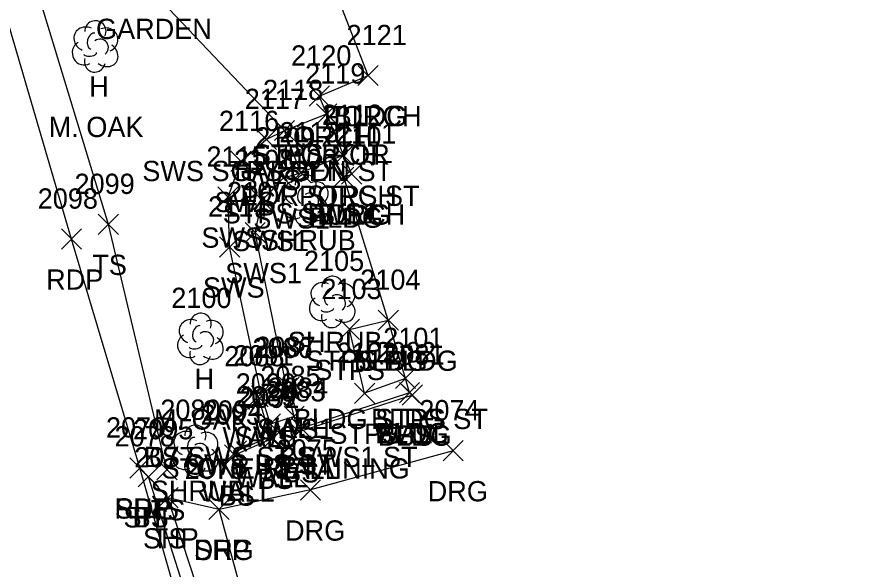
# Model space of a CAD drawing. Extents: x 1620157 to 1620595, y 115111 to 117885.
# Drawn here: x 1620251.8 to 1620336.2, y 115691.4 to 115746 of the extents above; entities that cross this region are included whole.
import ezdxf

# ---------------------------------------------------------------- set-up
doc = ezdxf.new("R2010")
doc.units = 0
for name, color, linetype in [('L_A', 7, 'Continuous'), ('L_C', 7, 'Continuous'), ('L_I', 7, 'Continuous'), ('L_TIC', 7, 'Continuous'), ('LAPB', 7, 'Continuous'), ('LBC', 7, 'Continuous'), ('LBF', 7, 'Continuous'), ('LELB', 7, 'Continuous'), ('LSH', 7, 'Continuous'), ('LTD', 7, 'Continuous'), ('LW', 7, 'Continuous'), ('P_A', 7, 'Continuous'), ('P_I', 7, 'Continuous'), ('P_TIC', 7, 'Continuous'), ('PET', 7, 'Continuous'), ('PSP', 7, 'Continuous'), ('R_A', 7, 'Continuous'), ('R_I', 7, 'Continuous'), ('R_TIC', 7, 'Continuous'), ('RDG', 7, 'Continuous'), ('RSW', 7, 'Continuous')]:
    doc.layers.add(name, color=color, linetype=linetype)

msp = doc.modelspace()

# ---------------------------------------------------------------- linework, layer by layer
at = {"layer": 'L_TIC'}
for points in [[(1620285.479, 115739.19), (1620287.479, 115741.19)], [(1620287.479, 115739.19), (1620285.479, 115741.19)], [(1620285.479, 115739.19), (1620287.479, 115741.19)], [(1620287.479, 115739.19), (1620285.479, 115741.19)], [(1620280.656, 115737.169), (1620282.656, 115739.169)], [(1620282.656, 115737.169), (1620280.656, 115739.169)], [(1620281.394, 115735.396), (1620283.394, 115737.396)], [(1620283.394, 115735.396), (1620281.394, 115737.396)], [(1620281.394, 115735.396), (1620283.394, 115737.396)], [(1620283.394, 115735.396), (1620281.394, 115737.396)], [(1620277.224, 115733.768), (1620279.224, 115735.768)], [(1620279.224, 115733.768), (1620277.224, 115735.768)], [(1620277.224, 115733.768), (1620279.224, 115735.768)], [(1620279.224, 115733.768), (1620277.224, 115735.768)], [(1620283.041, 115731.322), (1620285.041, 115733.322)], [(1620285.041, 115731.322), (1620283.041, 115733.322)], [(1620283.041, 115731.322), (1620285.041, 115733.322)], [(1620285.041, 115731.322), (1620283.041, 115733.322)], [(1620278.843, 115729.594), (1620280.843, 115731.594)], [(1620280.843, 115729.594), (1620278.843, 115731.594)], [(1620283.066, 115729.16), (1620285.066, 115731.16)], [(1620285.066, 115729.16), (1620283.066, 115731.16)], [(1620283.863, 115729.466), (1620285.863, 115731.466)], [(1620285.863, 115729.466), (1620283.863, 115731.466)], [(1620283.863, 115729.466), (1620285.863, 115731.466)], [(1620285.863, 115729.466), (1620283.863, 115731.466)], [(1620259.835, 115724.502), (1620261.835, 115726.502)], [(1620261.835, 115724.502), (1620259.835, 115726.502)], [(1620287.473, 115715.044), (1620289.473, 115717.044)], [(1620289.473, 115715.044), (1620287.473, 115717.044)], [(1620287.473, 115715.044), (1620289.473, 115717.044)], [(1620289.473, 115715.044), (1620287.473, 115717.044)], [(1620283.642, 115714.129), (1620285.642, 115716.129)], [(1620285.642, 115714.129), (1620283.642, 115716.129)], [(1620289.174, 115709.294), (1620291.174, 115711.294)], [(1620291.174, 115709.294), (1620289.174, 115711.294)], [(1620289.174, 115709.294), (1620291.174, 115711.294)], [(1620291.174, 115709.294), (1620289.174, 115711.294)], [(1620277.686, 115708.413), (1620279.686, 115710.413)], [(1620279.686, 115708.413), (1620277.686, 115710.413)], [(1620285.139, 115707.835), (1620287.139, 115709.835)], [(1620287.139, 115707.835), (1620285.139, 115709.835)], [(1620289.565, 115707.888), (1620291.565, 115709.888)], [(1620291.565, 115707.888), (1620289.565, 115709.888)], [(1620289.565, 115707.888), (1620291.565, 115709.888)], [(1620291.565, 115707.888), (1620289.565, 115709.888)], [(1620274.614, 115707.49), (1620276.614, 115709.49)], [(1620276.614, 115707.49), (1620274.614, 115709.49)], [(1620289.85, 115707.651), (1620291.85, 115709.651)], [(1620291.85, 115707.651), (1620289.85, 115709.651)], [(1620289.85, 115707.651), (1620291.85, 115709.651)], [(1620291.85, 115707.651), (1620289.85, 115709.651)], [(1620278.18, 115705.543), (1620280.18, 115707.543)], [(1620280.18, 115705.543), (1620278.18, 115707.543)], [(1620275.83, 115704.795), (1620277.83, 115706.795)], [(1620277.83, 115704.795), (1620275.83, 115706.795)], [(1620278.906, 115704.377), (1620280.906, 115706.377)], [(1620280.906, 115704.377), (1620278.906, 115706.377)], [(1620275.799, 115703.54), (1620277.799, 115705.54)], [(1620277.799, 115703.54), (1620275.799, 115705.54)], [(1620278.653, 115704.023), (1620280.653, 115706.023)], [(1620280.653, 115704.023), (1620278.653, 115706.023)], [(1620276.094, 115703.385), (1620278.094, 115705.385)], [(1620278.094, 115703.385), (1620276.094, 115705.385)], [(1620272.482, 115702.127), (1620274.482, 115704.127)], [(1620274.482, 115702.127), (1620272.482, 115704.127)], [(1620272.286, 115701.732), (1620274.286, 115703.732)], [(1620274.286, 115701.732), (1620272.286, 115703.732)], [(1620265.612, 115700.283), (1620267.612, 115702.283)], [(1620267.612, 115700.283), (1620265.612, 115702.283)], [(1620263.785, 115699.582), (1620265.785, 115701.582)], [(1620265.785, 115699.582), (1620263.785, 115701.582)], [(1620265.718, 115697.512), (1620267.718, 115699.512)], [(1620267.718, 115697.512), (1620265.718, 115699.512)]]:
    msp.add_lwpolyline(points, dxfattribs=at)
at = {"layer": 'LAPB'}
msp.add_lwpolyline([(1620278.224, 115734.768), (1620264.941, 115748.796), (1620257.681, 115770.754)], dxfattribs=at)
at = {"layer": 'LBC'}
for points in [[(1620286.479, 115740.19), (1620278.676, 115760.26), (1620273.221, 115758.055), (1620271.644, 115761.629), (1620268.392, 115762.369), (1620266.542, 115766.833), (1620268.468, 115769.831), (1620266.748, 115774.206), (1620264.771, 115779.101), (1620264.248, 115780.999)], [(1620290.85, 115708.651), (1620290.565, 115708.888), (1620290.174, 115710.294), (1620288.473, 115716.044), (1620284.066, 115730.16), (1620284.863, 115730.466)]]:
    msp.add_lwpolyline(points, dxfattribs=at)
at = {"layer": 'LBF'}
for points in [[(1620284.863, 115730.466), (1620284.041, 115732.322), (1620282.394, 115736.396), (1620281.656, 115738.169), (1620286.479, 115740.19)], [(1620284.041, 115732.322), (1620279.843, 115730.594), (1620278.224, 115734.768), (1620282.394, 115736.396)], [(1620290.174, 115710.294), (1620286.139, 115708.835), (1620284.642, 115715.129), (1620288.473, 115716.044)]]:
    msp.add_lwpolyline(points, dxfattribs=at)
at = {"layer": 'LELB'}
for points in [[(1620266.612, 115701.283), (1620260.835, 115725.502), (1620244.29, 115779.748)], [(1620290.85, 115708.651), (1620279.653, 115705.023), (1620279.18, 115706.543)], [(1620276.83, 115705.795), (1620277.094, 115704.385), (1620273.286, 115702.732)], [(1620284.85, 115634.911), (1620272.284, 115677.072), (1620264.785, 115700.582)], [(1620274.466, 115674.837), (1620266.718, 115698.512)]]:
    msp.add_lwpolyline(points, dxfattribs=at)
at = {"layer": 'LSH'}
for p, q in [((1620280.261, 115727.94), (1620280.261, 115727.94)), ((1620280.261, 115727.94), (1620280.261, 115727.94)), ((1620282.915, 115717.895), (1620282.915, 115717.895)), ((1620282.915, 115717.895), (1620282.915, 115717.895)), ((1620269.385, 115703.207), (1620269.385, 115703.207)), ((1620269.385, 115703.207), (1620269.385, 115703.207))]:
    msp.add_line(p, q, dxfattribs=at)
for centre in [(1620280.308, 115729.374), (1620282.961, 115719.329), (1620269.432, 115704.641)]:
    msp.add_arc(centre, 1.047, 335.52715, 180.95627, dxfattribs=at)
for centre, major_axis, ratio, start_param, end_param in [((1620279.47, 115728.606), (1.21, -0.512), 0.895232, 1.570796, 4.712389), ((1620280.053, 115728.398), (-0.208, -0.792), 0.645439, 3.141593, 6.283185), ((1620281.303, 115728.523), (-1.141, -0.483), 0.949671, 1.570796, 4.712389), ((1620280.762, 115727.773), (-0.5, 0.667), 0.989748, 3.141593, 6.283185), ((1620279.178, 115727.231), (0.584, -1.042), 0.959034, 3.141593, 6.283185), ((1620281.262, 115727.106), (-1.09, 0.792), 0.841452, 1.570796, 4.712389), ((1620280.262, 115726.44), (0.265, 1.061), 0.942809, 1.570796, 4.712389), ((1620279.803, 115727.19), (-0.625, -0.083), 0.423636, 0, 3.141593), ((1620282.123, 115718.561), (1.21, -0.512), 0.895232, 1.570796, 4.712389), ((1620282.706, 115718.353), (-0.208, -0.792), 0.645439, 3.141593, 6.283185), ((1620283.956, 115718.478), (-1.141, -0.483), 0.949671, 1.570796, 4.712389), ((1620281.832, 115717.186), (0.584, -1.042), 0.959034, 3.141593, 6.283185), ((1620283.415, 115717.728), (-0.5, 0.667), 0.989748, 3.141593, 6.283185), ((1620283.915, 115717.062), (-1.09, 0.792), 0.841452, 1.570796, 4.712389), ((1620282.915, 115716.395), (0.265, 1.061), 0.942809, 1.570796, 4.712389), ((1620282.457, 115717.145), (-0.625, -0.083), 0.423636, 0, 3.141593), ((1620268.593, 115703.873), (1.21, -0.512), 0.895232, 1.570796, 4.712389), ((1620270.427, 115703.79), (-1.141, -0.483), 0.949671, 1.570796, 4.712389), ((1620269.177, 115703.665), (-0.208, -0.792), 0.645439, 3.141593, 6.283185), ((1620269.885, 115703.04), (-0.5, 0.667), 0.989748, 3.141593, 6.283185), ((1620268.302, 115702.498), (0.584, -1.042), 0.959034, 3.141593, 6.283185), ((1620270.385, 115702.373), (-1.09, 0.792), 0.841452, 1.570796, 4.712389), ((1620268.927, 115702.457), (-0.625, -0.083), 0.423636, 0, 3.141593), ((1620269.385, 115701.707), (0.265, 1.061), 0.942809, 1.570796, 4.712389)]:
    msp.add_ellipse(centre, major_axis=major_axis, ratio=ratio, start_param=start_param, end_param=end_param, dxfattribs=at)
at = {"layer": 'LTD'}
for p, q in [((1620259.508, 115743.117), (1620259.508, 115743.117)), ((1620259.508, 115743.117), (1620259.508, 115743.117)), ((1620269.905, 115714.244), (1620269.905, 115714.244)), ((1620269.905, 115714.244), (1620269.905, 115714.244))]:
    msp.add_line(p, q, dxfattribs=at)
for centre in [(1620259.555, 115744.551), (1620269.952, 115715.678)]:
    msp.add_arc(centre, 1.047, 335.52715, 180.95627, dxfattribs=at)
for centre, major_axis, ratio, start_param, end_param in [((1620258.717, 115743.783), (1.21, -0.512), 0.895232, 1.570796, 4.712389), ((1620259.3, 115743.575), (-0.208, -0.792), 0.645439, 3.141593, 6.283185), ((1620260.55, 115743.7), (-1.141, -0.483), 0.949671, 1.570796, 4.712389), ((1620260.008, 115742.95), (-0.5, 0.667), 0.989748, 3.141593, 6.283185), ((1620258.425, 115742.408), (0.584, -1.042), 0.959034, 3.141593, 6.283185), ((1620260.508, 115742.284), (-1.09, 0.792), 0.841452, 1.570796, 4.712389), ((1620259.509, 115741.617), (0.265, 1.061), 0.942809, 1.570796, 4.712389), ((1620259.05, 115742.367), (-0.625, -0.083), 0.423636, 0, 3.141593), ((1620269.114, 115714.91), (1.21, -0.512), 0.895232, 1.570796, 4.712389), ((1620270.947, 115714.827), (-1.141, -0.483), 0.949671, 1.570796, 4.712389), ((1620269.697, 115714.702), (-0.208, -0.792), 0.645439, 3.141593, 6.283185), ((1620270.405, 115714.077), (-0.5, 0.667), 0.989748, 3.141593, 6.283185), ((1620268.822, 115713.535), (0.584, -1.042), 0.959034, 3.141593, 6.283185), ((1620270.905, 115713.411), (-1.09, 0.792), 0.841452, 1.570796, 4.712389), ((1620269.447, 115713.494), (-0.625, -0.083), 0.423636, 0, 3.141593), ((1620269.906, 115712.744), (0.265, 1.061), 0.942809, 1.570796, 4.712389)]:
    msp.add_ellipse(centre, major_axis=major_axis, ratio=ratio, start_param=start_param, end_param=end_param, dxfattribs=at)
at = {"layer": 'LW'}
for points in [[(1620290.565, 115708.888), (1620279.906, 115705.377), (1620278.686, 115709.413)], [(1620275.614, 115708.49), (1620276.799, 115704.54), (1620273.482, 115703.127)]]:
    msp.add_lwpolyline(points, dxfattribs=at)
at = {"layer": 'P_TIC'}
for points in [[(1620256.196, 115723.05), (1620258.196, 115725.05)], [(1620258.196, 115723.05), (1620256.196, 115725.05)], [(1620262.941, 115700.458), (1620264.941, 115702.458)], [(1620264.941, 115700.458), (1620262.941, 115702.458)], [(1620262.941, 115700.458), (1620264.941, 115702.458)], [(1620264.941, 115700.458), (1620262.941, 115702.458)], [(1620263.785, 115699.582), (1620265.785, 115701.582)], [(1620265.785, 115699.582), (1620263.785, 115701.582)], [(1620265.718, 115697.512), (1620267.718, 115699.512)], [(1620267.718, 115697.512), (1620265.718, 115699.512)], [(1620270.765, 115696.364), (1620272.765, 115698.364)], [(1620272.765, 115696.364), (1620270.765, 115698.364)]]:
    msp.add_lwpolyline(points, dxfattribs=at)
at = {"layer": 'PET'}
msp.add_lwpolyline([(1620336.223, 115456.795), (1620332.523, 115469.32), (1620324.589, 115500.95), (1620318.089, 115527.231), (1620313.062, 115541.759), (1620309.737, 115554.427), (1620302.898, 115574.327), (1620297.627, 115590.435), (1620296.31, 115595.422), (1620295.446, 115598.549), (1620285.025, 115631.411), (1620284.003, 115634.579), (1620271.049, 115676.547), (1620263.941, 115701.458), (1620257.196, 115724.05), (1620247.856, 115755.871), (1620237.557, 115791.502), (1620229.867, 115820.365), (1620222.522, 115845.456)], dxfattribs=at)
at = {"layer": 'PSP'}
msp.add_lwpolyline([(1620284.003, 115634.579), (1620284.85, 115634.911), (1620285.305, 115636.206), (1620274.466, 115674.837), (1620275.53, 115678.066), (1620276.548, 115679.801), (1620271.765, 115697.364), (1620266.718, 115698.512), (1620264.785, 115700.582), (1620263.941, 115701.458)], dxfattribs=at)
at = {"layer": 'R_TIC'}
for points in [[(1620277.224, 115733.768), (1620279.224, 115735.768)], [(1620279.224, 115733.768), (1620277.224, 115735.768)], [(1620275.422, 115732.886), (1620277.422, 115734.886)], [(1620277.422, 115732.886), (1620275.422, 115734.886)], [(1620272.928, 115730.714), (1620274.928, 115732.714)], [(1620274.928, 115730.714), (1620272.928, 115732.714)], [(1620277.109, 115729.087), (1620279.109, 115731.087)], [(1620279.109, 115729.087), (1620277.109, 115731.087)], [(1620278.843, 115729.594), (1620280.843, 115731.594)], [(1620280.843, 115729.594), (1620278.843, 115731.594)], [(1620271.646, 115727.194), (1620273.646, 115729.194)], [(1620273.646, 115727.194), (1620271.646, 115729.194)], [(1620275.018, 115726.863), (1620277.018, 115728.863)], [(1620277.018, 115726.863), (1620275.018, 115728.863)], [(1620274.331, 115723.694), (1620276.331, 115725.694)], [(1620276.331, 115723.694), (1620274.331, 115725.694)], [(1620271.799, 115722.267), (1620273.799, 115724.267)], [(1620273.799, 115722.267), (1620271.799, 115724.267)], [(1620277.457, 115708.306), (1620279.457, 115710.306)], [(1620279.457, 115708.306), (1620277.457, 115710.306)], [(1620274.953, 115707.566), (1620276.953, 115709.566)], [(1620276.953, 115707.566), (1620274.953, 115709.566)], [(1620278.18, 115705.543), (1620280.18, 115707.543)], [(1620280.18, 115705.543), (1620278.18, 115707.543)], [(1620278.18, 115705.543), (1620280.18, 115707.543)], [(1620280.18, 115705.543), (1620278.18, 115707.543)], [(1620275.83, 115704.795), (1620277.83, 115706.795)], [(1620277.83, 115704.795), (1620275.83, 115706.795)], [(1620293.874, 115702.163), (1620295.874, 115704.163)], [(1620295.874, 115702.163), (1620293.874, 115704.163)], [(1620279.788, 115698.282), (1620281.788, 115700.282)], [(1620281.788, 115698.282), (1620279.788, 115700.282)], [(1620270.765, 115696.364), (1620272.765, 115698.364)], [(1620272.765, 115696.364), (1620270.765, 115698.364)]]:
    msp.add_lwpolyline(points, dxfattribs=at)
at = {"layer": 'RDG'}
msp.add_lwpolyline([(1620294.874, 115703.163), (1620280.788, 115699.282), (1620271.765, 115697.364)], dxfattribs=at)
at = {"layer": 'RSW'}
for points in [[(1620279.18, 115706.543), (1620276.83, 115705.795), (1620275.953, 115708.566), (1620272.799, 115723.267), (1620272.646, 115728.194), (1620273.928, 115731.714), (1620276.422, 115733.886), (1620278.224, 115734.768)], [(1620279.18, 115706.543), (1620278.457, 115709.306), (1620275.331, 115724.694), (1620276.018, 115727.863), (1620278.109, 115730.087), (1620279.843, 115730.594)]]:
    msp.add_lwpolyline(points, dxfattribs=at)

# ---------------------------------------------------------------- texts
at = {"layer": 'L_A'}
for s, p in [('GARDEN', (1620259.611, 115743.796)), ('H', (1620258.941, 115738.117)), ('PORCH', (1620282.101, 115735.19)), ('BLDG', (1620283.069, 115735.19)), ('PORCH', (1620277.278, 115733.169)), ('STPS POR', (1620275.094, 115731.396)), ('PORCH', (1620278.016, 115731.396)), ('SWS STPS GDN ST', (1620264.185, 115729.768)), ('GARDEN', (1620272.893, 115729.768)), ('POR STPS ST', (1620273.876, 115727.322)), ('PORCH', (1620279.663, 115727.322)), ('STPS SWS1', (1620272.127, 115725.594)), ('PORCH', (1620280.485, 115725.466)), ('BLDG', (1620281.454, 115725.466)), ('BLDG', (1620280.656, 115725.16)), ('SHRUB', (1620275.891, 115722.94)), ('TS', (1620259.244, 115720.502)), ('SHRUB', (1620278.545, 115712.895)), ('STPS BLDG', (1620280.308, 115711.044)), ('BLDG', (1620285.064, 115711.044)), ('STPS', (1620281.161, 115710.129)), ('H', (1620269.338, 115709.244)), ('BLDG STPS ST', (1620279.142, 115705.294)), ('BLDG', (1620286.764, 115705.294)), ('WALL', (1620275.174, 115704.413)), ('STPS', (1620282.659, 115703.835)), ('WALL', (1620287.053, 115703.888)), ('BLDG', (1620287.155, 115703.888)), ('BLDG', (1620287.441, 115703.651)), ('BS', (1620289.291, 115703.651)), ('WALL', (1620272.102, 115703.49)), ('BS', (1620277.621, 115701.543)), ('BS', (1620275.271, 115700.795)), ('WALL', (1620276.394, 115700.377)), ('WALL', (1620273.287, 115699.54)), ('BS', (1620275.535, 115699.385)), ('BS', (1620278.094, 115700.023)), ('SHRUB', (1620265.015, 115698.207)), ('WALL', (1620269.971, 115698.127)), ('BS', (1620271.727, 115697.732)), ('TS', (1620265.021, 115696.283)), ('BS', (1620263.226, 115695.582)), ('TS', (1620265.128, 115693.512))]:
    msp.add_text(s, height=2, dxfattribs=at).set_placement(p)
at = {"layer": 'L_C'}
for s, p in [('M. OAK', (1620254.942, 115734.117)), ('M. OAK', (1620265.338, 115705.244)), ('STONE RETAINING', (1620266.08, 115700.413))]:
    msp.add_text(s, height=2, dxfattribs=at).set_placement(p)
at = {"layer": 'L_I'}
for s, p in [('2121', (1620284.353, 115743.19)), ('2121', (1620284.353, 115743.19)), ('2120', (1620278.877, 115741.169)), ('2119', (1620280.26, 115739.396)), ('2119', (1620280.26, 115739.396)), ('2118', (1620276.098, 115737.768)), ('2118', (1620276.098, 115737.768)), ('2112', (1620281.915, 115735.322)), ('2112', (1620281.915, 115735.322)), ('2113', (1620277.717, 115733.594)), ('2110', (1620281.853, 115733.16)), ('2111', (1620283.305, 115733.466)), ('2111', (1620283.305, 115733.466)), ('2106', (1620277.435, 115730.94)), ('2099', (1620257.488, 115728.502)), ('2105', (1620280.143, 115720.895)), ('2104', (1620285.702, 115719.044)), ('2104', (1620285.702, 115719.044)), ('2103', (1620281.87, 115718.129)), ('2100', (1620267.047, 115717.244)), ('2101', (1620287.969, 115713.294)), ('2101', (1620287.969, 115713.294)), ('2087', (1620275.348, 115712.413)), ('2088', (1620272.276, 115711.49)), ('2102', (1620283.368, 115711.835)), ('2082', (1620287.226, 115711.888)), ('2082', (1620287.226, 115711.888)), ('2081', (1620288.079, 115711.651)), ('2081', (1620288.079, 115711.651)), ('2085', (1620275.842, 115709.543)), ('2090', (1620273.405, 115708.795)), ('2083', (1620276.315, 115708.023)), ('2084', (1620276.567, 115708.377)), ('2089', (1620273.453, 115707.54)), ('2092', (1620273.756, 115707.385)), ('2080', (1620265.96, 115706.207)), ('2094', (1620270.144, 115706.127)), ('2093', (1620269.948, 115705.732)), ('2078', (1620261.447, 115703.582)), ('2095', (1620263.273, 115704.283)), ('2077', (1620263.38, 115701.512))]:
    msp.add_text(s, height=2, dxfattribs=at).set_placement(p)
at = {"layer": 'P_A'}
for s, p in [('RDP', (1620254.684, 115719.05)), ('SHP', (1620261.476, 115696.458)), ('RDP', (1620261.429, 115696.458)), ('SHP', (1620262.321, 115695.582)), ('SHP', (1620264.254, 115693.512)), ('SHP', (1620269.3, 115692.364))]:
    msp.add_text(s, height=2, dxfattribs=at).set_placement(p)
at = {"layer": 'P_I'}
for s, p in [('2098', (1620253.857, 115727.05)), ('2079', (1620260.594, 115704.458)), ('2079', (1620260.594, 115704.458)), ('2078', (1620261.447, 115703.582)), ('2077', (1620263.38, 115701.512)), ('2076', (1620268.371, 115700.364))]:
    msp.add_text(s, height=2, dxfattribs=at).set_placement(p)
at = {"layer": 'R_A'}
for s, p in [('SWS STPS GDN ST', (1620264.185, 115729.768)), ('SWS', (1620273.792, 115728.886)), ('SWS', (1620271.298, 115726.714)), ('STPS SWS1', (1620272.127, 115725.594)), ('SWS1', (1620275.148, 115725.087)), ('SWS', (1620270.016, 115723.194)), ('SWS1', (1620273.057, 115722.863)), ('SWS1', (1620272.37, 115719.694)), ('SWS', (1620270.169, 115718.267)), ('SWS', (1620273.323, 115703.566)), ('SWS1', (1620275.496, 115704.306)), ('BS SWS ST SWS1 ST', (1620264.323, 115701.543)), ('BS SWS ST SWS1 ST', (1620264.323, 115701.543)), ('SWS BS ST', (1620268.492, 115700.795)), ('DRG', (1620292.362, 115698.163)), ('DRG', (1620278.277, 115694.282)), ('DRG', (1620269.253, 115692.364))]:
    msp.add_text(s, height=2, dxfattribs=at).set_placement(p)
at = {"layer": 'R_I'}
for s, p in [('2118', (1620276.098, 115737.768)), ('2117', (1620274.296, 115736.886)), ('2116', (1620271.747, 115734.714)), ('2109', (1620275.33, 115733.087)), ('2113', (1620277.717, 115733.594)), ('2115', (1620270.52, 115731.194)), ('2108', (1620273.246, 115730.863)), ('2107', (1620272.56, 115727.694)), ('2114', (1620270.674, 115726.267)), ('2086', (1620275.063, 115712.306)), ('2091', (1620273.181, 115711.566)), ('2085', (1620275.842, 115709.543)), ('2085', (1620275.842, 115709.543)), ('2090', (1620273.405, 115708.795)), ('2074', (1620291.536, 115706.163)), ('2075', (1620277.45, 115702.282)), ('2076', (1620268.371, 115700.364))]:
    msp.add_text(s, height=2, dxfattribs=at).set_placement(p)

doc.saveas('drawing.dxf')
